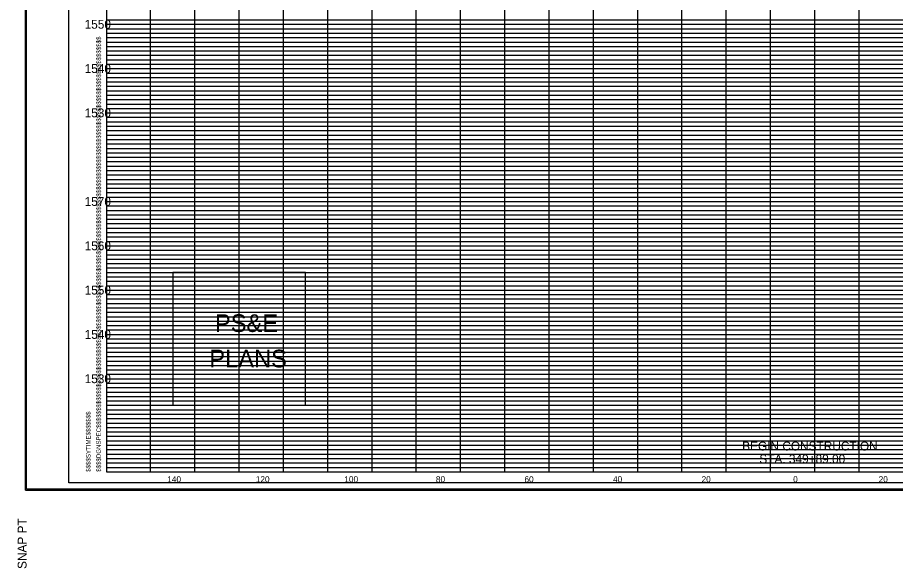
# Model space of a CAD drawing. Extents: x 980 to 1375, y 978 to 1227.
# Drawn here: x 979.9 to 1178.2, y 978.2 to 1102.5 of the extents above; entities that cross this region are included whole.
import ezdxf

# ---------------------------------------------------------------- set-up
doc = ezdxf.new("R2010")
doc.units = 0
for name, color, linetype in [('DESIGN - SHEET - Corner Text', 7, 'Continuous'), ('DESIGN - SHEET - Light Grid', 7, 'Continuous'), ('DESIGN - SHEET - Linework', 7, 'Continuous'), ('DESIGN - SHEET - Plot Shape', 7, 'Continuous'), ('DESIGN - TYPICAL - Text', 7, 'Continuous')]:
    doc.layers.add(name, color=color, linetype=linetype)

msp = doc.modelspace()

# ---------------------------------------------------------------- linework, layer by layer
at = {"layer": 'DESIGN - SHEET - Corner Text'}
msp.add_lwpolyline([(1015, 1045), (1015, 1015), (1045, 1015), (1045, 1045)], close=True, dxfattribs=at)
at = {"layer": 'DESIGN - SHEET - Light Grid'}
for p, q in [((1000, 1102), (1080, 1102)), ((1000, 1101), (1080, 1101)), ((1080, 1102), (1160, 1102)), ((1080, 1101), (1160, 1101)), ((1160, 1102), (1240, 1102)), ((1160, 1101), (1240, 1101)), ((1000, 1099), (1080, 1099)), ((1080, 1099), (1160, 1099)), ((1160, 1099), (1240, 1099)), ((1000, 1098), (1080, 1098)), ((1000, 1097), (1080, 1097)), ((1080, 1098), (1160, 1098)), ((1080, 1097), (1160, 1097)), ((1160, 1098), (1240, 1098)), ((1160, 1097), (1240, 1097)), ((1000, 1096), (1080, 1096)), ((1000, 1095), (1080, 1095)), ((1080, 1096), (1160, 1096)), ((1080, 1095), (1160, 1095)), ((1160, 1096), (1240, 1096)), ((1160, 1095), (1240, 1095)), ((1000, 1094), (1080, 1094)), ((1000, 1093), (1080, 1093)), ((1080, 1094), (1160, 1094)), ((1080, 1093), (1160, 1093)), ((1160, 1094), (1240, 1094)), ((1160, 1093), (1240, 1093)), ((1000, 1092), (1080, 1092)), ((1000, 1091), (1080, 1091)), ((1080, 1092), (1160, 1092)), ((1080, 1091), (1160, 1091)), ((1160, 1092), (1240, 1092)), ((1160, 1091), (1240, 1091)), ((1000, 1089), (1080, 1089)), ((1080, 1089), (1160, 1089)), ((1160, 1089), (1240, 1089)), ((1000, 1088), (1080, 1088)), ((1000, 1087), (1080, 1087)), ((1080, 1088), (1160, 1088)), ((1080, 1087), (1160, 1087)), ((1160, 1088), (1240, 1088)), ((1160, 1087), (1240, 1087)), ((1000, 1086), (1080, 1086)), ((1000, 1085), (1080, 1085)), ((1080, 1086), (1160, 1086)), ((1080, 1085), (1160, 1085)), ((1160, 1086), (1240, 1086)), ((1160, 1085), (1240, 1085)), ((1000, 1084), (1080, 1084)), ((1000, 1083), (1080, 1083)), ((1080, 1084), (1160, 1084)), ((1080, 1083), (1160, 1083)), ((1160, 1084), (1240, 1084)), ((1160, 1083), (1240, 1083)), ((1000, 1082), (1080, 1082)), ((1000, 1081), (1080, 1081)), ((1080, 1082), (1160, 1082)), ((1080, 1081), (1160, 1081)), ((1160, 1082), (1240, 1082)), ((1160, 1081), (1240, 1081)), ((1000, 1079), (1080, 1079)), ((1080, 1079), (1160, 1079)), ((1160, 1079), (1240, 1079)), ((1000, 1078), (1080, 1078)), ((1000, 1077), (1080, 1077)), ((1080, 1078), (1160, 1078)), ((1080, 1077), (1160, 1077)), ((1160, 1078), (1240, 1078)), ((1160, 1077), (1240, 1077)), ((1000, 1076), (1080, 1076)), ((1000, 1075), (1080, 1075)), ((1080, 1076), (1160, 1076)), ((1080, 1075), (1160, 1075)), ((1160, 1076), (1240, 1076)), ((1160, 1075), (1240, 1075)), ((1000, 1074), (1080, 1074)), ((1000, 1073), (1080, 1073)), ((1080, 1074), (1160, 1074)), ((1080, 1073), (1160, 1073)), ((1160, 1074), (1240, 1074)), ((1160, 1073), (1240, 1073)), ((1000, 1072), (1080, 1072)), ((1000, 1071), (1080, 1071)), ((1080, 1072), (1160, 1072)), ((1080, 1071), (1160, 1071)), ((1160, 1072), (1240, 1072)), ((1160, 1071), (1240, 1071)), ((1000, 1069), (1080, 1069)), ((1080, 1069), (1160, 1069)), ((1160, 1069), (1240, 1069)), ((1000, 1068), (1080, 1068)), ((1000, 1067), (1080, 1067)), ((1080, 1068), (1160, 1068)), ((1080, 1067), (1160, 1067)), ((1160, 1068), (1240, 1068)), ((1160, 1067), (1240, 1067)), ((1000, 1066), (1080, 1066)), ((1000, 1065), (1080, 1065)), ((1080, 1066), (1160, 1066)), ((1080, 1065), (1160, 1065)), ((1160, 1066), (1240, 1066)), ((1160, 1065), (1240, 1065)), ((1000, 1064), (1080, 1064)), ((1000, 1063), (1080, 1063)), ((1080, 1064), (1160, 1064)), ((1080, 1063), (1160, 1063)), ((1160, 1064), (1240, 1064)), ((1160, 1063), (1240, 1063)), ((1000, 1062), (1080, 1062)), ((1000, 1061), (1080, 1061)), ((1080, 1062), (1160, 1062)), ((1080, 1061), (1160, 1061)), ((1160, 1062), (1240, 1062)), ((1160, 1061), (1240, 1061)), ((1000, 1059), (1080, 1059)), ((1080, 1059), (1160, 1059)), ((1160, 1059), (1240, 1059)), ((1000, 1058), (1080, 1058)), ((1000, 1057), (1080, 1057)), ((1080, 1058), (1160, 1058)), ((1080, 1057), (1160, 1057)), ((1160, 1058), (1240, 1058)), ((1160, 1057), (1240, 1057)), ((1000, 1056), (1080, 1056)), ((1000, 1055), (1080, 1055)), ((1080, 1056), (1160, 1056)), ((1080, 1055), (1160, 1055)), ((1160, 1056), (1240, 1056)), ((1160, 1055), (1240, 1055)), ((1000, 1054), (1080, 1054)), ((1000, 1053), (1080, 1053)), ((1080, 1054), (1160, 1054)), ((1080, 1053), (1160, 1053)), ((1160, 1054), (1240, 1054)), ((1160, 1053), (1240, 1053)), ((1000, 1052), (1080, 1052)), ((1000, 1051), (1080, 1051)), ((1080, 1052), (1160, 1052)), ((1080, 1051), (1160, 1051)), ((1160, 1052), (1240, 1052)), ((1160, 1051), (1240, 1051)), ((1000, 1049), (1080, 1049)), ((1080, 1049), (1160, 1049)), ((1160, 1049), (1240, 1049)), ((1000, 1048), (1080, 1048)), ((1000, 1047), (1080, 1047)), ((1080, 1048), (1160, 1048)), ((1080, 1047), (1160, 1047)), ((1160, 1048), (1240, 1048)), ((1160, 1047), (1240, 1047)), ((1000, 1046), (1080, 1046)), ((1000, 1045), (1080, 1045)), ((1080, 1046), (1160, 1046)), ((1080, 1045), (1160, 1045)), ((1160, 1046), (1240, 1046)), ((1160, 1045), (1240, 1045)), ((1000, 1044), (1080, 1044)), ((1000, 1043), (1080, 1043)), ((1080, 1044), (1160, 1044)), ((1080, 1043), (1160, 1043)), ((1160, 1044), (1240, 1044)), ((1160, 1043), (1240, 1043)), ((1000, 1042), (1080, 1042)), ((1000, 1041), (1080, 1041)), ((1080, 1042), (1160, 1042)), ((1080, 1041), (1160, 1041)), ((1160, 1042), (1240, 1042)), ((1160, 1041), (1240, 1041)), ((1000, 1039), (1080, 1039)), ((1080, 1039), (1160, 1039)), ((1160, 1039), (1240, 1039)), ((1000, 1038), (1080, 1038)), ((1000, 1037), (1080, 1037)), ((1080, 1038), (1160, 1038)), ((1080, 1037), (1160, 1037)), ((1160, 1038), (1240, 1038)), ((1160, 1037), (1240, 1037)), ((1000, 1036), (1080, 1036)), ((1080, 1036), (1160, 1036)), ((1160, 1036), (1240, 1036)), ((1000, 1035), (1080, 1035)), ((1000, 1034), (1080, 1034)), ((1080, 1035), (1160, 1035)), ((1080, 1034), (1160, 1034)), ((1160, 1035), (1240, 1035)), ((1160, 1034), (1240, 1034)), ((1000, 1033), (1080, 1033)), ((1000, 1032), (1080, 1032)), ((1080, 1033), (1160, 1033)), ((1080, 1032), (1160, 1032)), ((1160, 1033), (1240, 1033)), ((1160, 1032), (1240, 1032)), ((1000, 1031), (1080, 1031)), ((1080, 1031), (1160, 1031)), ((1160, 1031), (1240, 1031)), ((1000, 1029), (1080, 1029)), ((1000, 1028), (1080, 1028)), ((1080, 1029), (1160, 1029)), ((1080, 1028), (1160, 1028)), ((1160, 1029), (1240, 1029)), ((1160, 1028), (1240, 1028)), ((1000, 1027), (1080, 1027)), ((1000, 1026), (1080, 1026)), ((1080, 1027), (1160, 1027)), ((1080, 1026), (1160, 1026)), ((1160, 1027), (1240, 1027)), ((1160, 1026), (1240, 1026)), ((1000, 1025), (1080, 1025)), ((1000, 1024), (1080, 1024)), ((1080, 1025), (1160, 1025)), ((1080, 1024), (1160, 1024)), ((1160, 1025), (1240, 1025)), ((1160, 1024), (1240, 1024)), ((1000, 1023), (1080, 1023)), ((1000, 1022), (1080, 1022)), ((1080, 1023), (1160, 1023)), ((1080, 1022), (1160, 1022)), ((1160, 1023), (1240, 1023)), ((1160, 1022), (1240, 1022)), ((1000, 1021), (1080, 1021)), ((1080, 1021), (1160, 1021)), ((1160, 1021), (1240, 1021)), ((1000, 1019), (1080, 1019)), ((1000, 1018), (1080, 1018)), ((1080, 1019), (1160, 1019)), ((1080, 1018), (1160, 1018)), ((1160, 1019), (1240, 1019)), ((1160, 1018), (1240, 1018)), ((1000, 1017), (1080, 1017)), ((1000, 1016), (1080, 1016)), ((1080, 1017), (1160, 1017)), ((1080, 1016), (1160, 1016)), ((1160, 1017), (1240, 1017)), ((1160, 1016), (1240, 1016)), ((1000, 1015), (1080, 1015)), ((1000, 1014), (1080, 1014)), ((1080, 1015), (1160, 1015)), ((1080, 1014), (1160, 1014)), ((1160, 1015), (1240, 1015)), ((1160, 1014), (1240, 1014)), ((1000, 1013), (1080, 1013)), ((1000, 1012), (1080, 1012)), ((1080, 1013), (1160, 1013)), ((1080, 1012), (1160, 1012)), ((1160, 1013), (1240, 1013)), ((1160, 1012), (1240, 1012)), ((1000, 1011), (1080, 1011)), ((1080, 1011), (1160, 1011)), ((1160, 1011), (1240, 1011)), ((1000, 1009), (1080, 1009)), ((1000, 1008), (1080, 1008)), ((1080, 1009), (1160, 1009)), ((1080, 1008), (1160, 1008)), ((1160, 1009), (1240, 1009)), ((1160, 1008), (1240, 1008)), ((1000, 1007), (1080, 1007)), ((1000, 1006), (1080, 1006)), ((1080, 1007), (1160, 1007)), ((1080, 1006), (1160, 1006)), ((1160, 1007), (1240, 1007)), ((1160, 1006), (1240, 1006)), ((1000, 1005), (1080, 1005)), ((1000, 1004), (1080, 1004)), ((1080, 1005), (1160, 1005)), ((1080, 1004), (1160, 1004)), ((1160, 1005), (1240, 1005)), ((1160, 1004), (1240, 1004)), ((1000, 1003), (1080, 1003)), ((1000, 1002), (1080, 1002)), ((1080, 1003), (1160, 1003)), ((1080, 1002), (1160, 1002)), ((1160, 1003), (1240, 1003)), ((1160, 1002), (1240, 1002)), ((1000, 1001), (1080, 1001)), ((1080, 1001), (1160, 1001)), ((1160, 1001), (1240, 1001))]:
    msp.add_line(p, q, dxfattribs=at)
at = {"layer": 'DESIGN - SHEET - Linework'}
for p, q in [((981.77, 995.86), (981.77, 1214.14)), ((1010, 1000), (1010, 1210)), ((1020, 1000), (1020, 1210)), ((1030, 1000), (1030, 1210)), ((1040, 1000), (1040, 1210)), ((1050, 1000), (1050, 1210)), ((1060, 1000), (1060, 1210)), ((1070, 1000), (1070, 1210)), ((1080, 1000), (1080, 1210)), ((1090, 1000), (1090, 1210)), ((1100, 1000), (1100, 1210)), ((1110, 1000), (1110, 1210)), ((1120, 1000), (1120, 1210)), ((1130, 1000), (1130, 1210)), ((1140, 1000), (1140, 1210)), ((1150, 1000), (1150, 1210)), ((1160, 1000), (1160, 1210)), ((1170, 1000), (1170, 1210)), ((1000, 1100), (1320, 1100)), ((1000, 1090), (1320, 1090)), ((1000, 1080), (1320, 1080)), ((1000, 1070), (1320, 1070)), ((1000, 1060), (1320, 1060)), ((1000, 1050), (1320, 1050)), ((1000, 1040), (1320, 1040)), ((1000, 1030), (1320, 1030)), ((1000, 1020), (1320, 1020)), ((1000, 1010), (1320, 1010)), ((981.77, 995.86), (1322.17, 995.86))]:
    msp.add_line(p, q, dxfattribs=at)
msp.add_lwpolyline([(1000, 1210), (1000, 1000), (1320, 1000), (1320, 1210), (1000, 1210)], dxfattribs=at)
at = {"layer": 'DESIGN - SHEET - Plot Shape'}
for points in [[(981.97, 1213.94), (1321.97, 1213.94), (1321.97, 996.06), (981.97, 996.06)], [(991.5, 1210), (1320, 1210), (1320, 997.5), (991.5, 997.5)]]:
    msp.add_lwpolyline(points, close=True, dxfattribs=at)

# ---------------------------------------------------------------- texts
at = {"layer": 'DESIGN - SHEET - Corner Text'}
for s, height, p in [('$$$$DGNSPEC$$$$$$$$$$$$$$$$$$$$$$$$$$$$$$$$$$$$$$$$$$$$$$$$$$$$$$$$$$$$$$$$$$$$$$$$$$$$$$$$$$$$$$$$$$$$$$$$$$$$$$$$$$$$$$$$$$$', 1.00002, (998.74, 1000)), ('$$$$SYTIME$$$$$$$', 1, (996.42, 1000)), ('SNAP PT  ', 2, (981.97, 978.06))]:
    msp.add_text(s, height=height, rotation=90, dxfattribs=at).set_placement(p)
for s, p in [('PS&E ', (1024.52, 1031.55)), ('PLANS', (1023.24, 1023.55))]:
    msp.add_text(s, height=4, dxfattribs=at).set_placement(p)
at = {"layer": 'DESIGN - TYPICAL - Text'}
for s, height, p in [('     1550     ', 2, (991.37, 1100)), ('     1540     ', 2, (991.37, 1090)), ('     1530     ', 2, (991.37, 1080)), ('     1570     ', 2, (991.37, 1060)), ('     1560     ', 2, (991.37, 1050)), ('     1550     ', 2, (991.37, 1040)), ('     1540     ', 2, (991.37, 1030)), ('     1530     ', 2, (991.37, 1020)), ('BEGIN CONSTRUCTION', 2, (1143.6, 1004.8)), ('STA. 349+89.00', 2, (1147.47, 1001.9)), ('     140     ', 1.4, (1011.14, 997.6)), ('     120     ', 1.4, (1031.14, 997.6)), ('     100     ', 1.4, (1051.14, 997.6)), ('     80     ', 1.4, (1071.82, 997.6)), ('     60     ', 1.4, (1091.82, 997.6)), ('     40     ', 1.4, (1111.82, 997.6)), ('     20     ', 1.4, (1131.82, 997.6)), ('     0     ', 1.4, (1152.51, 997.6)), ('     0     ', 1.4, (1152.51, 997.6)), ('     20     ', 1.4, (1171.82, 997.6))]:
    msp.add_text(s, height=height, dxfattribs=at).set_placement(p)

doc.saveas('drawing.dxf')
